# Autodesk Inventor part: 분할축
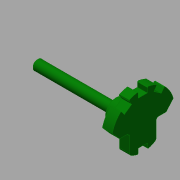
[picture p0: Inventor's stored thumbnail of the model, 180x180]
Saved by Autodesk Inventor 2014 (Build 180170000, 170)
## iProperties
Created: 2016-11
Part Number: 분할축
Material: 강철, 연강
Document SubType Name: Modeling
Designer: mduedu
Density: 1 g/cm^3
Appearance: Dark Green
Author: mduedu
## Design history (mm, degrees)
sketch "스케치1"
  geometry: C1 r 38 at (0, 0); 1 further point
  constraints: 1 centre point, 1 coincident
  dimensions: "d0" = 76 diameter of C1
extrude "돌출1" new body sketch "스케치1" distance "d1" = 12; taper "d2" = 0 deg
sketch "스케치2"
  geometry: L1 (0, 38)-(0, -38); L2 (5.5, 37.6)-(5.5, 31); L3 (5.5, 31)-(-5.5, 31); L4 (-5.5, 31)-(-5.5, 37.6); A1 r 38 centre (0, 0) between (0, 38) and (0, -38) reference; A2 r 38 centre (0, 0) between (5.5, 37.6) and (-5.5, 37.6); 2 further points
  constraints: 8 end point, 6 point on circle, 2 coincident, 2 vertical, 1 centre point, 1 horizontal, 1 midpoint, 1 parallel, 1 symmetric about line
  dimensions: "d3" = 11 distance of L2.end L3.end; "d5" = 31 distance from line of L3 point (0, 0)
extrude "돌출2" cut sketch "스케치2" stored distance "d7" = 12; taper "d8" = 0 deg
sketch "스케치3"
  geometry: L1 (-16, 0)-(-38, 0); L2 (16, 0)-(38, 0); L3 (0, -28)-(0, 28); L4 (-16, -22.978)-(-16, 0); L5 (16, -22.978)-(16, 0); A1 r 38 centre (0, 0) between (-5.5, 37.6) and (-17.061, 33.955) reference; A2 r 38 centre (0, 0) between (-38, 0) and (38, 0); A3 r 28 centre (0, 0) between (-16, -22.978) and (16, -22.978); 4 further points
  constraints: 10 end point, 7 point on circle, 3 coincident, 2 centre point, 2 horizontal alignment, 2 midpoint, 2 parallel, 1 collinear, 1 horizontal, 1 perpendicular, 1 other
  dimensions: "d13" = 32 distance between parallel lines of L5 L4; "d14" = 28 radius of A3
extrude "돌출3" cut sketch "스케치3" stored distance "d15" = 12; taper "d16" = 0 deg
sketch "스케치4"
  geometry: L1 (0, 0)-(0, -28); L2 (5.5, -27.455)-(5.5, -21); L3 (5.5, -21)-(-5.5, -21); L4 (-5.5, -21)-(-5.5, -27.455); A1 r 28 centre (0, 0) between (-16, -22.978) and (16, -22.978) reference; A2 r 28 centre (0, 0) between (16, -22.978) and (0, -28); A3 r 28 centre (0, 0) between (-5.5, -27.455) and (5.5, -27.455); 1 further point
  constraints: 8 end point, 7 point on circle, 2 centre point, 2 coincident, 1 horizontal, 1 parallel, 1 other
  dimensions: "d17" = 11 distance between parallel lines of L2 L4; "d19" = 21 distance from line of L3 point (0, 0)
extrude "돌출4" cut sketch "스케치4" stored distance "d20" = 12; taper "d21" = 0 deg
sketch "스케치5"
  geometry: C1 r 13 at (0, 0); 1 further point
  constraints: 1 centre point, 1 coincident
  dimensions: "d22" = 26 diameter of C1
extrude "돌출5" join sketch "스케치5" distance "d23" = 20; taper "d24" = 0 deg
sketch "스케치6"
  geometry: C1 r 6 at (0, 0); 1 further point
  constraints: 1 centre point, 1 coincident
  dimensions: "d25" = 12 diameter of C1
extrude "돌출6" join sketch "스케치6" distance "d26" = 95; taper "d27" = 0 deg
fillet "모깎기1" dims "d28" = 3
chamfer "모따기1" distance "d29" = 1; stored, may be unused: second distance "d30" = 2, angle "d31" = 45 deg
sketch "스케치7"
  geometry: L1 (-20, 13)-(-20, -13) reference; L2 (-20, 6)-(-114, 6) reference; L3 (0, 0)-(-20, 0); C1 r 1 at (-21, 6)
  constraints: 2 end point, 1 centre point, 1 midpoint, 1 tangent
  dimensions: "d32" = 2 diameter of C1; "d33" = 10 dimension on C1 L3
revolve "회전1" sketch "스케치7" stored, may be unused: angle "d34" = 90 deg
chamfer "모따기2" distance "d35" = 1; stored, may be unused: second distance "d36" = 2, angle "d37" = 45 deg
chamfer "모따기3" distance "d38" = 10; stored, may be unused: second distance "d39" = 2, angle "d40" = 45 deg
chamfer "모따기4" distance "d41" = 1; stored, may be unused: second distance "d42" = 2, angle "d43" = 45 deg
fillet "모깎기2" dims "d44" = 3
node "솔리드1"
pattern_circular "원형 패턴1" dims angle "d10" = 35 deg
other parameters: "d12" = 56
